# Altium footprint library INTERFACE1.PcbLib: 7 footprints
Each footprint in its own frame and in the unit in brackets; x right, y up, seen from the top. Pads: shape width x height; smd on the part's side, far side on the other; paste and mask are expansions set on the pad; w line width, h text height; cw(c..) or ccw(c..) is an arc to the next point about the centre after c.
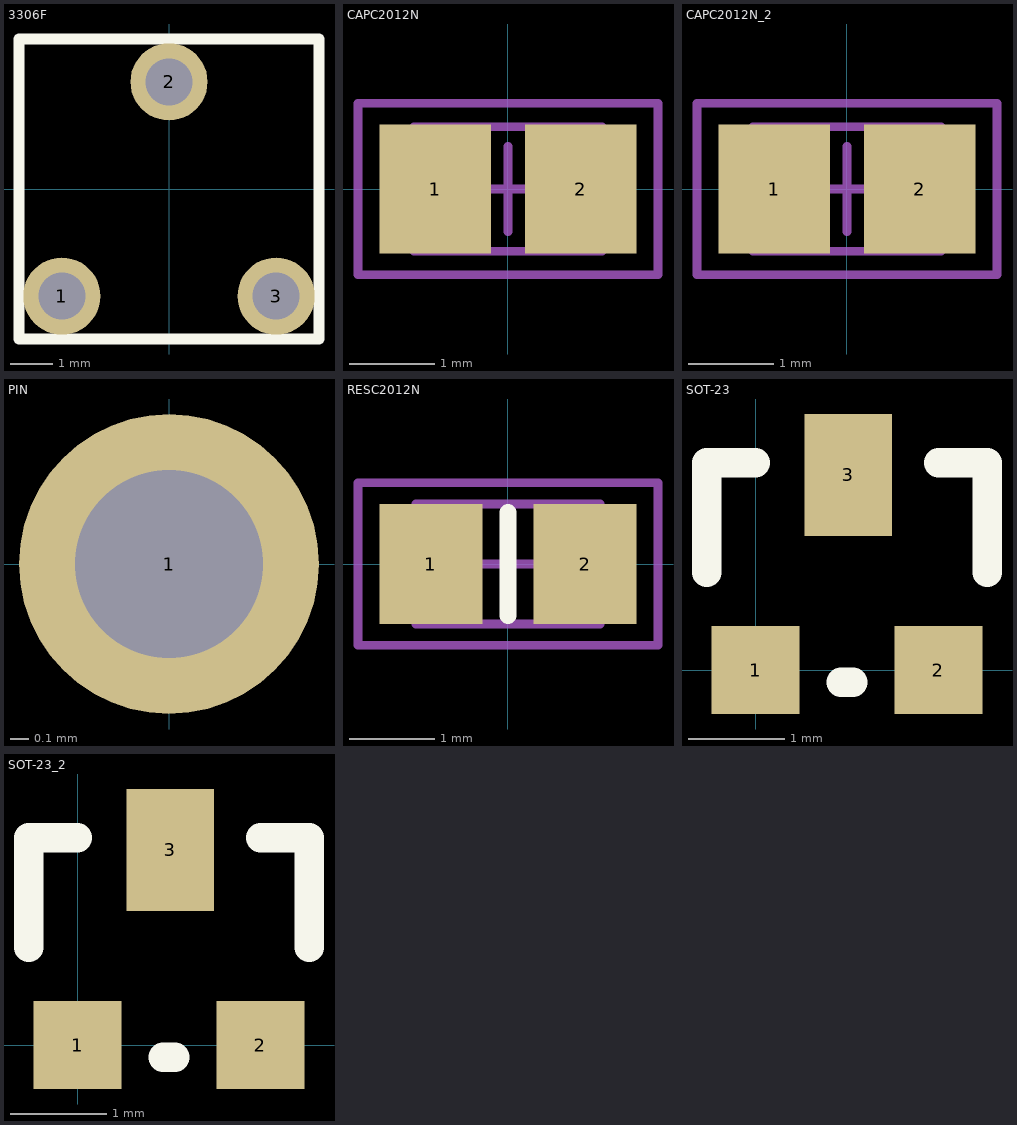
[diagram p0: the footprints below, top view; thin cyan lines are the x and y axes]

## 3306F [mm] "TRIMMER   Bourns Inc."
height 7.62
pads (3):
  round 1.8 hole 1.1: 1(-2.5,-2.5) 2(0,2.5) 3(2.5,-2.5)
Top Overlay:
  lines w0.254: -3.5,-3.5 3.5,-3.5 3.5,3.5 -3.5,3.5 -3.5,-3.5
3D body "Trimmer 3306F-1.STEP": height 7.62, standoff -3.04, extent -3.405,-4.876 3.405,3.375

## CAPC2012N [mm] "Chip Capacitor, Body 2.0x1.3mm, IPC Medium Density"
height 1.1
pads (2):
  rect 1.3x1.5 smd: 1(-0.85,0) 2(0.85,0)
Mechanical 13:
  lines w0.1: -1.1,-0.725 1.1,-0.725 1.1,0.725 -1.1,0.725 -1.1,-0.725
Mechanical 15:
  lines w0.1: -0.5,0 0.5,0 ; 0,-0.5 0,0.5 ; -1.75,-1 1.75,-1 1.75,1 -1.75,1 -1.75,-1
3D body "0805 SMD Capacitor.step": height 0.78, standoff 0, extent -1,-0.625 1,0.625

## CAPC2012N_2 [mm]
pads (2):
  rect 1.3x1.5 smd: 1(-0.85,0) 2(0.85,0)
Mechanical 13:
  lines w0.1: -1.1,-0.725 1.1,-0.725 1.1,0.725 -1.1,0.725 -1.1,-0.725
Mechanical 15:
  lines w0.1: -0.5,0 0.5,0 ; 0,-0.5 0,0.5 ; -1.75,-1 1.75,-1 1.75,1 -1.75,1 -1.75,-1
3D body "0805 SMD Capacitor.step": height 0.78, standoff 0, extent -1,-0.625 1,0.625

## PIN [mm]
height 3
pads (1):
  round 1.6 hole 1: 1(0,0)

## RESC2012N [mm] "Chip Resistor, Body 2.0x1.3mm, IPC Medium Density"
height 0.65
pads (2):
  rect 1.2x1.4 smd: 1(-0.9,0) 2(0.9,0)
Top Overlay:
  lines w0.2: 0,-0.6 0,0.6
Mechanical 13:
  lines w0.1: -1.075,-0.7 -1.075,0.7 1.075,0.7 1.075,-0.7 -1.075,-0.7
Mechanical 15:
  lines w0.1: -0.5,0 0.5,0 ; 0,-0.5 0,0.5 ; -1.75,-0.95 -1.75,0.95 1.75,0.95 1.75,-0.95 -1.75,-0.95
3D body "CR2012-0805.step": height 0.6, standoff 0, extent -1,-0.625 1,0.625

## SOT-23 [mil]
height 44.09
pads (3):
  rect 36x36 smd: 1(0,0) 2(75,0)
  rect 36x50 smd: 3(38,80)
Top Overlay:
  lines w12: -20,40 -20,85 0,85 ; 35,-5 40,-5 ; 75,85 95,85 95,40
3D body "SOT-23.step": height 43.31, standoff 0, extent -19.68,-9.84 98.43,88.58

## SOT-23_2 [mil]
pads (3):
  rect 36x36 smd: 1(0,0) 2(75,0)
  rect 36x50 smd: 3(38,80)
Top Overlay:
  lines w12: -20,40 -20,85 0,85 ; 35,-5 40,-5 ; 75,85 95,85 95,40
3D body "SOT-23.step": height 43.31, standoff 0, extent -19.68,-9.84 98.43,88.58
